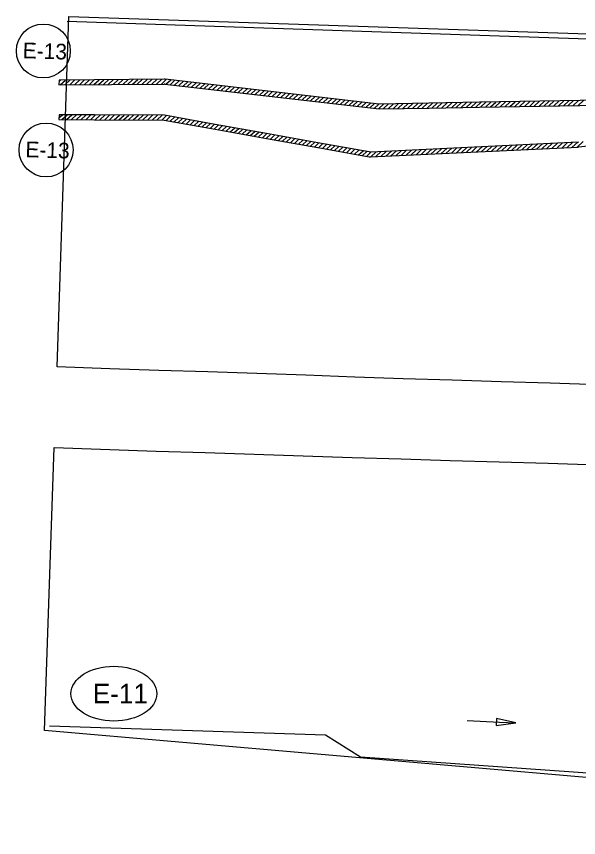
# Model space of a CAD drawing. Extents: x 977239 to 983725, y 1525948 to 1526901.
# Drawn here: x 977238.9 to 977411.1, y 1526389.8 to 1526641.5 of the extents above; entities that cross this region are included whole.
import ezdxf

# ---------------------------------------------------------------- set-up
doc = ezdxf.new("R2010")
doc.units = 0
for name, color, linetype in [('R_Erosion', 7, 'Continuous'), ('R_No Plot', 7, 'Continuous'), ('R_Water', 7, 'Continuous')]:
    doc.layers.add(name, color=color, linetype=linetype)

msp = doc.modelspace()

# ---------------------------------------------------------------- linework, layer by layer
at = {"layer": 'R_Erosion'}
for p, q in [((977254.39, 1526640.01), (977939.78, 1526617.04)), ((977251.95, 1526621.98), (977251.9, 1526620.48)), ((977251.9, 1526620.48), (977284.14, 1526620.77)), ((977251.94, 1526621.55), (977252.39, 1526621.98)), ((977284.19, 1526622.27), (977251.95, 1526621.98)), ((977284.19, 1526622.27), (977251.95, 1526621.98)), ((977252.25, 1526620.48), (977253.87, 1526621.99)), ((977253.73, 1526620.49), (977255.35, 1526622.01)), ((977255.21, 1526620.51), (977256.83, 1526622.02)), ((977256.69, 1526620.52), (977258.31, 1526622.03)), ((977258.17, 1526620.53), (977259.78, 1526622.05)), ((977259.64, 1526620.55), (977261.26, 1526622.06)), ((977261.12, 1526620.56), (977262.74, 1526622.07)), ((977262.6, 1526620.58), (977264.22, 1526622.09)), ((977264.08, 1526620.59), (977265.7, 1526622.1)), ((977265.56, 1526620.6), (977267.18, 1526622.12)), ((977267.04, 1526620.62), (977268.65, 1526622.13)), ((977268.51, 1526620.63), (977270.13, 1526622.14)), ((977269.99, 1526620.64), (977271.61, 1526622.16)), ((977271.47, 1526620.66), (977273.09, 1526622.17)), ((977272.95, 1526620.67), (977274.57, 1526622.18)), ((977274.43, 1526620.68), (977276.05, 1526622.2)), ((977275.91, 1526620.7), (977277.52, 1526622.21)), ((977277.38, 1526620.71), (977279, 1526622.22)), ((977278.86, 1526620.72), (977280.48, 1526622.24)), ((977280.34, 1526620.74), (977281.96, 1526622.25)), ((977281.82, 1526620.75), (977283.44, 1526622.27)), ((977283.3, 1526620.77), (977284.84, 1526622.21)), ((977284.71, 1526620.72), (977286.15, 1526622.06)), ((977286.02, 1526620.57), (977287.45, 1526621.91)), ((977287.32, 1526620.42), (977288.75, 1526621.76)), ((977288.62, 1526620.27), (977290.05, 1526621.61)), ((977289.92, 1526620.12), (977291.35, 1526621.45)), ((977291.22, 1526619.96), (977292.66, 1526621.3)), ((977292.53, 1526619.81), (977293.96, 1526621.15)), ((977293.83, 1526619.66), (977295.26, 1526621)), ((977295.13, 1526619.51), (977296.56, 1526620.85)), ((977296.43, 1526619.36), (977297.86, 1526620.7)), ((977297.73, 1526619.21), (977299.16, 1526620.55)), ((977299.04, 1526619.06), (977300.47, 1526620.39)), ((977300.34, 1526618.9), (977301.77, 1526620.24)), ((977301.64, 1526618.75), (977303.07, 1526620.09)), ((977302.94, 1526618.6), (977304.37, 1526619.94)), ((977304.24, 1526618.45), (977305.67, 1526619.79)), ((977305.55, 1526618.3), (977306.98, 1526619.64)), ((977306.85, 1526618.15), (977308.28, 1526619.49)), ((977308.15, 1526618), (977309.58, 1526619.33)), ((977309.45, 1526617.84), (977310.88, 1526619.18)), ((977310.75, 1526617.69), (977312.18, 1526619.03)), ((977312.06, 1526617.54), (977313.49, 1526618.88)), ((977313.36, 1526617.39), (977314.79, 1526618.73)), ((977314.66, 1526617.24), (977316.09, 1526618.58)), ((977315.96, 1526617.09), (977317.39, 1526618.43)), ((977317.26, 1526616.94), (977318.69, 1526618.27)), ((977318.56, 1526616.78), (977320, 1526618.12)), ((977319.87, 1526616.63), (977321.3, 1526617.97)), ((977321.17, 1526616.48), (977322.6, 1526617.82)), ((977322.47, 1526616.33), (977323.9, 1526617.67)), ((977323.77, 1526616.18), (977325.2, 1526617.52)), ((977325.07, 1526616.03), (977326.51, 1526617.37)), ((977326.38, 1526615.88), (977327.81, 1526617.21)), ((977327.68, 1526615.72), (977329.11, 1526617.06)), ((977328.98, 1526615.57), (977330.41, 1526616.91)), ((977330.28, 1526615.42), (977331.71, 1526616.76)), ((977331.58, 1526615.27), (977333.01, 1526616.61)), ((977332.89, 1526615.12), (977334.32, 1526616.46)), ((977334.19, 1526614.97), (977335.62, 1526616.31)), ((977335.49, 1526614.82), (977336.92, 1526616.15)), ((977336.79, 1526614.66), (977338.22, 1526616)), ((977338.09, 1526614.51), (977339.52, 1526615.85)), ((977339.4, 1526614.36), (977340.83, 1526615.7)), ((977340.7, 1526614.21), (977342.13, 1526615.55)), ((977342, 1526614.06), (977343.43, 1526615.4)), ((977385.59, 1526613.75), (977387.22, 1526615.28)), ((977387.08, 1526613.78), (977388.71, 1526615.3)), ((977388.57, 1526613.8), (977390.2, 1526615.33)), ((977390.06, 1526613.83), (977391.69, 1526615.36)), ((977391.55, 1526613.86), (977393.19, 1526615.38)), ((977393.04, 1526613.88), (977394.68, 1526615.41)), ((977394.54, 1526613.91), (977396.17, 1526615.44)), ((977396.03, 1526613.93), (977397.66, 1526615.46)), ((977397.52, 1526613.96), (977399.15, 1526615.49)), ((977399.01, 1526613.99), (977400.64, 1526615.51)), ((977400.5, 1526614.01), (977402.14, 1526615.54)), ((977402, 1526614.04), (977403.63, 1526615.57)), ((977403.49, 1526614.07), (977405.12, 1526615.59)), ((977404.98, 1526614.09), (977406.61, 1526615.62)), ((977406.47, 1526614.12), (977408.1, 1526615.65)), ((977407.96, 1526614.14), (977409.6, 1526615.67)), ((977409.45, 1526614.17), (977411.09, 1526615.7)), ((977410.95, 1526614.2), (977412.61, 1526615.75)), ((977343.3, 1526613.91), (977344.73, 1526615.25)), ((977344.6, 1526613.76), (977346.03, 1526615.09)), ((977345.91, 1526613.6), (977347.34, 1526614.94)), ((977347.21, 1526613.45), (977348.64, 1526614.79)), ((977348.51, 1526613.3), (977349.94, 1526614.64)), ((977349.81, 1526613.15), (977351.41, 1526614.65)), ((977351.27, 1526613.15), (977352.91, 1526614.68)), ((977352.77, 1526613.18), (977354.4, 1526614.7)), ((977354.26, 1526613.2), (977355.89, 1526614.73)), ((977355.75, 1526613.23), (977357.38, 1526614.75)), ((977357.24, 1526613.25), (977358.87, 1526614.78)), ((977358.73, 1526613.28), (977360.37, 1526614.81)), ((977360.23, 1526613.31), (977361.86, 1526614.83)), ((977361.72, 1526613.33), (977363.35, 1526614.86)), ((977363.21, 1526613.36), (977364.84, 1526614.89)), ((977364.7, 1526613.39), (977366.33, 1526614.91)), ((977366.19, 1526613.41), (977367.82, 1526614.94)), ((977367.68, 1526613.44), (977369.32, 1526614.96)), ((977369.18, 1526613.46), (977370.81, 1526614.99)), ((977370.67, 1526613.49), (977372.3, 1526615.02)), ((977372.16, 1526613.52), (977373.79, 1526615.04)), ((977373.65, 1526613.54), (977375.28, 1526615.07)), ((977375.14, 1526613.57), (977376.78, 1526615.1)), ((977376.63, 1526613.59), (977378.27, 1526615.12)), ((977378.13, 1526613.62), (977379.76, 1526615.15)), ((977379.62, 1526613.65), (977381.25, 1526615.17)), ((977381.11, 1526613.67), (977382.74, 1526615.2)), ((977382.6, 1526613.7), (977384.23, 1526615.23)), ((977384.09, 1526613.73), (977385.73, 1526615.25)), ((977251.95, 1526611.37), (977251.9, 1526609.87)), ((977251.95, 1526611.37), (977251.9, 1526609.87)), ((977251.91, 1526610.39), (977252.96, 1526611.36)), ((977252.82, 1526609.86), (977254.41, 1526611.36)), ((977254.27, 1526609.86), (977255.87, 1526611.35)), ((977255.73, 1526609.85), (977257.32, 1526611.34)), ((977257.18, 1526609.84), (977258.78, 1526611.33)), ((977258.64, 1526609.83), (977260.23, 1526611.32)), ((977260.1, 1526609.83), (977261.69, 1526611.32)), ((977261.55, 1526609.82), (977263.15, 1526611.31)), ((977263.01, 1526609.81), (977264.6, 1526611.3)), ((977264.46, 1526609.8), (977266.06, 1526611.29)), ((977265.92, 1526609.8), (977267.51, 1526611.29)), ((977267.37, 1526609.79), (977268.97, 1526611.28)), ((977268.83, 1526609.78), (977270.42, 1526611.27)), ((977270.28, 1526609.77), (977271.88, 1526611.26)), ((977271.74, 1526609.76), (977273.33, 1526611.26)), ((977273.2, 1526609.76), (977274.79, 1526611.25)), ((977274.65, 1526609.75), (977276.25, 1526611.24)), ((977276.11, 1526609.74), (977277.7, 1526611.23)), ((977277.56, 1526609.73), (977279.16, 1526611.22)), ((977279.02, 1526609.73), (977280.61, 1526611.22)), ((977280.47, 1526609.72), (977282.07, 1526611.21)), ((977281.93, 1526609.71), (977283.52, 1526611.2)), ((977283.39, 1526609.7), (977284.86, 1526611.09)), ((977284.74, 1526609.6), (977286.09, 1526610.87)), ((977285.97, 1526609.38), (977287.32, 1526610.65)), ((977287.2, 1526609.16), (977288.55, 1526610.43)), ((977288.43, 1526608.94), (977289.78, 1526610.21)), ((977289.65, 1526608.72), (977291.01, 1526609.99)), ((977290.88, 1526608.5), (977292.24, 1526609.77)), ((977292.11, 1526608.28), (977293.46, 1526609.55)), ((977293.34, 1526608.06), (977294.69, 1526609.33)), ((977294.57, 1526607.84), (977295.92, 1526609.11)), ((977295.8, 1526607.62), (977297.15, 1526608.89)), ((977297.03, 1526607.4), (977298.38, 1526608.67)), ((977298.25, 1526607.18), (977299.61, 1526608.45)), ((977299.48, 1526606.96), (977300.84, 1526608.23)), ((977300.71, 1526606.74), (977302.06, 1526608.01)), ((977301.94, 1526606.52), (977303.29, 1526607.79)), ((977303.17, 1526606.3), (977304.52, 1526607.57)), ((977304.4, 1526606.08), (977305.75, 1526607.35)), ((977305.63, 1526605.86), (977306.98, 1526607.13)), ((977306.85, 1526605.64), (977308.21, 1526606.91)), ((977308.08, 1526605.42), (977309.44, 1526606.69)), ((977309.31, 1526605.2), (977310.66, 1526606.47)), ((977310.54, 1526604.98), (977311.89, 1526606.25)), ((977311.77, 1526604.76), (977313.12, 1526606.03)), ((977313, 1526604.54), (977314.35, 1526605.81)), ((977314.23, 1526604.32), (977315.58, 1526605.59)), ((977315.45, 1526604.1), (977316.81, 1526605.37)), ((977316.68, 1526603.88), (977318.04, 1526605.15)), ((977317.91, 1526603.66), (977319.27, 1526604.93)), ((977319.14, 1526603.44), (977320.49, 1526604.71)), ((977320.37, 1526603.22), (977321.72, 1526604.49)), ((977321.6, 1526603), (977322.95, 1526604.27)), ((977322.83, 1526602.78), (977324.18, 1526604.05)), ((977324.05, 1526602.56), (977325.41, 1526603.83)), ((977325.28, 1526602.34), (977326.64, 1526603.61)), ((977326.51, 1526602.12), (977327.87, 1526603.39)), ((977327.74, 1526601.9), (977329.09, 1526603.17)), ((977328.97, 1526601.68), (977330.32, 1526602.95)), ((977330.2, 1526601.46), (977331.55, 1526602.73)), ((977347, 1526599.96), (977331.27, 1526602.78)), ((977347, 1526599.96), (977331.27, 1526602.78)), ((977347, 1526599.96), (977331.27, 1526602.78)), ((977411, 1526602.96), (977347.45, 1526599.93)), ((977411, 1526602.96), (977347.45, 1526599.93)), ((977411, 1526602.96), (977347.45, 1526599.93)), ((977404.53, 1526601.16), (977406.21, 1526602.73)), ((977406.07, 1526601.23), (977407.76, 1526602.81)), ((977407.61, 1526601.3), (977409.3, 1526602.88)), ((977409.16, 1526601.38), (977410.84, 1526602.95)), ((977410.7, 1526601.45), (977412.47, 1526603.11)), ((977411.06, 1526601.47), (977427.65, 1526603.21)), ((977411.06, 1526601.47), (977427.65, 1526603.21)), ((977331.22, 1526601.28), (977346.95, 1526598.46)), ((977331.22, 1526601.28), (977346.95, 1526598.46)), ((977331.43, 1526601.24), (977332.78, 1526602.51)), ((977332.66, 1526601.02), (977334.01, 1526602.29)), ((977333.88, 1526600.8), (977335.24, 1526602.07)), ((977335.11, 1526600.58), (977336.47, 1526601.85)), ((977336.34, 1526600.36), (977337.69, 1526601.63)), ((977337.57, 1526600.14), (977338.92, 1526601.41)), ((977338.8, 1526599.92), (977340.15, 1526601.19)), ((977340.03, 1526599.7), (977341.38, 1526600.97)), ((977341.26, 1526599.48), (977342.61, 1526600.75)), ((977342.48, 1526599.26), (977343.84, 1526600.53)), ((977343.71, 1526599.04), (977345.07, 1526600.31)), ((977347.4, 1526598.43), (977410.95, 1526601.46)), ((977347.4, 1526598.43), (977410.95, 1526601.46)), ((977352.08, 1526598.65), (977353.77, 1526600.23)), ((977353.63, 1526598.73), (977355.31, 1526600.3)), ((977355.17, 1526598.8), (977356.85, 1526600.38)), ((977356.71, 1526598.87), (977358.4, 1526600.45)), ((977358.25, 1526598.95), (977359.94, 1526600.53)), ((977359.8, 1526599.02), (977361.48, 1526600.6)), ((977361.34, 1526599.1), (977363.02, 1526600.67)), ((977362.88, 1526599.17), (977364.57, 1526600.75)), ((977364.42, 1526599.24), (977366.11, 1526600.82)), ((977365.97, 1526599.32), (977367.65, 1526600.89)), ((977367.51, 1526599.39), (977369.19, 1526600.97)), ((977369.05, 1526599.46), (977370.74, 1526601.04)), ((977370.59, 1526599.54), (977372.28, 1526601.11)), ((977372.14, 1526599.61), (977373.82, 1526601.19)), ((977373.68, 1526599.68), (977375.36, 1526601.26)), ((977375.22, 1526599.76), (977376.91, 1526601.33)), ((977376.76, 1526599.83), (977378.45, 1526601.41)), ((977378.31, 1526599.9), (977379.99, 1526601.48)), ((977379.85, 1526599.98), (977381.53, 1526601.56)), ((977381.39, 1526600.05), (977383.08, 1526601.63)), ((977382.93, 1526600.13), (977384.62, 1526601.7)), ((977384.48, 1526600.2), (977386.16, 1526601.78)), ((977386.02, 1526600.27), (977387.7, 1526601.85)), ((977387.56, 1526600.35), (977389.25, 1526601.92)), ((977389.1, 1526600.42), (977390.79, 1526602)), ((977390.65, 1526600.49), (977392.33, 1526602.07)), ((977392.19, 1526600.57), (977393.87, 1526602.14)), ((977393.73, 1526600.64), (977395.42, 1526602.22)), ((977395.27, 1526600.71), (977396.96, 1526602.29)), ((977396.82, 1526600.79), (977398.5, 1526602.36)), ((977398.36, 1526600.86), (977400.04, 1526602.44)), ((977399.9, 1526600.93), (977401.59, 1526602.51)), ((977401.44, 1526601.01), (977403.13, 1526602.59)), ((977402.99, 1526601.08), (977404.67, 1526602.66)), ((977344.94, 1526598.82), (977346.29, 1526600.09)), ((977346.17, 1526598.6), (977347.6, 1526599.94)), ((977347.46, 1526598.43), (977349.14, 1526600.01)), ((977349, 1526598.51), (977350.68, 1526600.08)), ((977350.54, 1526598.58), (977352.23, 1526600.16)), ((977249.06, 1526424.07), (977333.59, 1526421.23)), ((977333.59, 1526421.23), (977344.28, 1526414.51))]:
    msp.add_line(p, q, dxfattribs=at)
for points in [[(977284.39, 1526620.76), (977350.01, 1526613.13), (977365.29, 1526613.4)], [(977365.34, 1526614.89), (977350.06, 1526614.63), (977284.44, 1526622.26)], [(977365.34, 1526614.89), (977350.06, 1526614.63), (977284.44, 1526622.26)], [(977365.29, 1526613.4), (977380.71, 1526613.67), (977411.52, 1526614.21), (977443.29, 1526615.68)], [(977443.34, 1526617.18), (977411.57, 1526615.71), (977380.76, 1526615.16), (977365.34, 1526614.89)], [(977443.34, 1526617.18), (977411.57, 1526615.71), (977380.76, 1526615.16), (977365.34, 1526614.89)], [(977262.77, 1526611.31), (977251.95, 1526611.37)], [(977262.77, 1526611.31), (977251.95, 1526611.37)], [(977262.77, 1526611.31), (977251.95, 1526611.37)], [(977299.8, 1526608.41), (977284.24, 1526611.2), (977262.77, 1526611.31)], [(977299.8, 1526608.41), (977284.24, 1526611.2), (977262.77, 1526611.31)], [(977299.8, 1526608.41), (977284.24, 1526611.2), (977262.77, 1526611.31)], [(977251.9, 1526609.87), (977262.72, 1526609.81)], [(977251.9, 1526609.87), (977262.72, 1526609.81)], [(977262.72, 1526609.81), (977284.19, 1526609.7), (977299.75, 1526606.91)], [(977262.72, 1526609.81), (977284.19, 1526609.7), (977299.75, 1526606.91)], [(977331.27, 1526602.78), (977315.54, 1526605.59), (977299.8, 1526608.41)], [(977331.27, 1526602.78), (977315.54, 1526605.59), (977299.8, 1526608.41)], [(977331.27, 1526602.78), (977315.54, 1526605.59), (977299.8, 1526608.41)], [(977299.75, 1526606.91), (977315.49, 1526604.09), (977331.22, 1526601.28)], [(977299.75, 1526606.91), (977315.49, 1526604.09), (977331.22, 1526601.28)], [(977344.28, 1526414.51), (977476.25, 1526405.26), (977627.5, 1526391.74)]]:
    msp.add_lwpolyline(points, dxfattribs=at)
for centre in [(977247.14, 1526630.9), (977247.97, 1526600.56)]:
    msp.add_circle(centre, 8.26, dxfattribs=at)
for centre, start, end in [((977284.16, 1526618.77), 83.3651, 90.5264), ((977284.21, 1526620.27), 83.3651, 90.5264), ((977284.21, 1526620.27), 83.3651, 90.5264), ((977365.33, 1526611.4), 91.0032, 91.0068), ((977365.38, 1526612.9), 91.0032, 91.0068), ((977262.78, 1526613.31), 269.6956, 269.6982), ((977262.73, 1526611.81), 269.6956, 269.6982), ((977300.16, 1526610.38), 259.8458, 259.8494), ((977300.11, 1526608.88), 259.8458, 259.8494), ((977331.62, 1526604.74), 259.8458, 259.8494), ((977410.9, 1526604.96), 272.7317, 275.9734), ((977410.9, 1526604.96), 272.7317, 275.9734), ((977410.9, 1526604.96), 272.7317, 275.9734), ((977331.57, 1526603.24), 259.8458, 259.8494), ((977410.85, 1526603.46), 272.7317, 275.9734), ((977410.85, 1526603.46), 272.7317, 275.9734), ((977347.31, 1526600.43), 259.8494, 272.7317), ((977347.31, 1526600.43), 259.8494, 272.7317), ((977347.36, 1526601.93), 259.8494, 272.7317), ((977347.36, 1526601.93), 259.8494, 272.7317), ((977347.36, 1526601.93), 259.8494, 272.7317)]:
    msp.add_arc(centre, 2, start, end, dxfattribs=at)
msp.add_ellipse((977268.75, 1526433.88), major_axis=(13.15, 0), ratio=0.638788, dxfattribs=at)
at = {"layer": 'R_No Plot'}
for p, q in [((977251.34, 1526534.04), (977254.94, 1526641.49)), ((977254.94, 1526641.49), (977938.33, 1526618.59)), ((977247.52, 1526422.58), (977250.42, 1526509.31)), ((977626.12, 1526389.78), (977247.52, 1526422.58))]:
    msp.add_line(p, q, dxfattribs=at)
for points in [[(977537.45, 1526524.26), (977522.46, 1526524.83), (977507.49, 1526525.25), (977492.51, 1526525.72), (977477.52, 1526526.38), (977462.53, 1526526.99), (977447.54, 1526527.56), (977432.55, 1526528.17), (977417.37, 1526528.57), (977402.38, 1526529.08), (977387.39, 1526529.46), (977372.4, 1526530.04), (977357.4, 1526530.44), (977342.6, 1526530.94), (977327.51, 1526531.53), (977312.52, 1526532.01), (977297.53, 1526532.51), (977282.53, 1526533), (977267.54, 1526533.48), (977251.34, 1526534.04)], [(977250.42, 1526509.31), (977281.73, 1526508.26), (977296.73, 1526507.77), (977311.72, 1526507.26), (977326.71, 1526506.76), (977341.77, 1526506.3), (977356.77, 1526505.85), (977371.76, 1526505.39), (977386.75, 1526504.91), (977401.75, 1526504.52), (977416.74, 1526504.01), (977431.58, 1526503.52), (977446.56, 1526502.91), (977461.55, 1526502.34), (977476.54, 1526501.74), (977491.53, 1526501.21), (977506.52, 1526500.67), (977521.54, 1526500.19), (977536.53, 1526499.66)]]:
    msp.add_lwpolyline(points, dxfattribs=at)
for centre in [(977247.14, 1526630.9), (977247.14, 1526630.9), (977247.97, 1526600.56)]:
    msp.add_circle(centre, 8.26, dxfattribs=at)
at = {"layer": 'R_Water'}
for p, q in [((977385.99, 1526426.3), (977385.88, 1526424.18)), ((977385.88, 1526424.18), (977391.93, 1526424.95)), ((977391.93, 1526424.95), (977385.99, 1526426.3))]:
    msp.add_line(p, q, dxfattribs=at)
msp.add_lwpolyline([(977376.95, 1526425.68), (977386.9, 1526425.19), (977391.93, 1526424.95)], dxfattribs=at)

# ---------------------------------------------------------------- texts
at = {"layer": 'R_Erosion'}
for p in [(977240.74, 1526628.71), (977241.57, 1526598.37)]:
    msp.add_text('E-13', height=4.8, rotation=358.0901, dxfattribs=at).set_placement(p)
msp.add_text('E-11', height=5.999, dxfattribs=at).set_placement((977262.25, 1526430.93))

doc.saveas('drawing.dxf')
